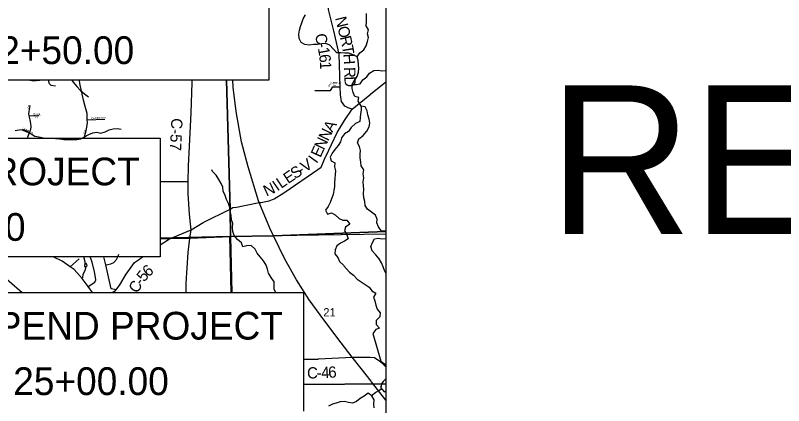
# Model space of a CAD drawing. Extents: x -37878.7 to -37844.7, y -19791.4 to -19769.4.
# Drawn here: x -37871.021 to -37867.14, y -19774.84 to -19772.87 of the extents above; entities that cross this region are included whole.
import ezdxf

# ---------------------------------------------------------------- set-up
doc = ezdxf.new("R2010")
doc.units = 0
for name, color, linetype in [('GM_X_City_Street', 7, 'Continuous'), ('GM_X_County_Road', 7, 'Continuous'), ('GM_X_County_Road_Text', 7, 'Continuous'), ('GM_X_Major_Lake', 7, 'Continuous'), ('GM_X_Minor_Lake', 7, 'Continuous'), ('GM_X_Minor_River', 7, 'Continuous'), ('GM_X_Section', 7, 'Continuous'), ('GM_X_Section_Text', 7, 'Continuous'), ('GM_X_State_Route', 7, 'Continuous'), ('GM_X_Township', 7, 'Continuous'), ('GM_X_Township_Road', 7, 'Continuous'), ('GM_X_Township_Subdivision', 7, 'Continuous'), ('GM_X_Township_Subdivision_Text', 7, 'Continuous'), ('GM_X_US_Route', 7, 'Continuous'), ('SH_Data', 7, 'Continuous'), ('TX_P_1', 7, 'Continuous')]:
    doc.layers.add(name, color=color, linetype=linetype)

msp = doc.modelspace()

# ---------------------------------------------------------------- linework, layer by layer
at = {"layer": 'GM_X_City_Street'}
for points in [[(-37870.6319, -19774.2693), (-37870.6537, -19774.2394), (-37870.6835, -19774.1987), (-37870.7235, -19774.1535), (-37870.7435, -19774.14), (-37870.7853, -19774.1117), (-37870.8292, -19774.0898)], [(-37870.7435, -19774.14), (-37870.6984, -19774.0985)], [(-37870.6537, -19774.2394), (-37870.6204, -19774.2173), (-37870.6146, -19774.2048), (-37870.6154, -19774.1939), (-37870.6212, -19774.1655), (-37870.6337, -19774.1162), (-37870.6432, -19774.0898)], [(-37870.5111, -19774.2563), (-37870.5369, -19774.2507), (-37870.5648, -19774.13), (-37870.5735, -19774.0898)], [(-37870.5648, -19774.13), (-37870.5544, -19774.1284), (-37870.5394, -19774.1251), (-37870.5235, -19774.1176), (-37870.5093, -19774.1025), (-37870.5026, -19774.0884), (-37870.4976, -19774.0758)], [(-37870.5327, -19774.2693), (-37870.5148, -19774.2586)], [(-37869.2072, -19774.5982), (-37869.1792, -19774.6162), (-37869.1585, -19774.6358)], [(-37869.1585, -19774.6358), (-37869.1504, -19774.6435)]]:
    msp.add_lwpolyline(points, dxfattribs=at)
at = {"layer": 'GM_X_County_Road'}
for points in [[(-37869.319, -19773.3445), (-37869.3398, -19773.3377), (-37869.3575, -19773.3294), (-37869.3736, -19773.3047), (-37869.3786, -19773.2714), (-37869.3799, -19773.2307), (-37869.3849, -19773.0657), (-37869.4128, -19772.9481), (-37869.4394, -19772.8412), (-37869.4519, -19772.4565), (-37869.4538, -19772.4162), (-37869.4608, -19772.3816)], [(-37870.1489, -19773.71), (-37870.1459, -19773.6301), (-37870.1407, -19773.5329), (-37870.1335, -19773.3623), (-37870.1286, -19773.2093), (-37870.1283, -19773.1975)], [(-37869.2267, -19773.269), (-37869.2266, -19773.2689), (-37869.1504, -19773.2056)], [(-37869.4529, -19773.5819), (-37869.3952, -19773.4624), (-37869.3584, -19773.4006), (-37869.319, -19773.3445), (-37869.2305, -19773.2721), (-37869.2267, -19773.269)], [(-37869.6604, -19773.7632), (-37869.4924, -19773.6483), (-37869.4768, -19773.6361), (-37869.4541, -19773.5846), (-37869.4537, -19773.5837), (-37869.4529, -19773.5819)], [(-37870.1489, -19773.71), (-37870.2888, -19773.711)], [(-37870.1334, -19773.9533), (-37870.1367, -19773.9231), (-37870.1422, -19773.8738), (-37870.1478, -19773.7705), (-37870.1489, -19773.71)], [(-37869.7801, -19773.8142), (-37869.7562, -19773.8106), (-37869.7396, -19773.8062), (-37869.7129, -19773.7965), (-37869.6655, -19773.7667), (-37869.6604, -19773.7632)], [(-37869.9224, -19773.8403), (-37869.9219, -19773.84), (-37869.9045, -19773.838), (-37869.7894, -19773.8156), (-37869.7801, -19773.8142)], [(-37870.2888, -19774.0279), (-37870.248, -19774.0013), (-37870.2371, -19773.9966), (-37870.1932, -19773.9774), (-37870.1334, -19773.9533), (-37870.0716, -19773.9158), (-37869.9361, -19773.8486), (-37869.9224, -19773.8403)], [(-37870.1393, -19773.9974), (-37870.1389, -19773.9947), (-37870.1334, -19773.9533)], [(-37870.3971, -19774.1033), (-37870.387, -19774.0962), (-37870.3781, -19774.0898)], [(-37870.5148, -19774.2586), (-37870.5111, -19774.2563), (-37870.4927, -19774.2309), (-37870.461, -19774.1768), (-37870.4187, -19774.1186), (-37870.3992, -19774.1048), (-37870.3971, -19774.1033)], [(-37869.489, -19774.6049), (-37869.3202, -19774.5956), (-37869.2976, -19774.5954)], [(-37869.2976, -19774.5954), (-37869.2293, -19774.5949), (-37869.2072, -19774.5982)], [(-37869.5652, -19774.6051), (-37869.4915, -19774.605), (-37869.489, -19774.6049)]]:
    msp.add_lwpolyline(points, dxfattribs=at)
at = {"layer": 'GM_X_Major_Lake'}
msp.add_line((-37869.3626, -19774.1343), (-37869.334, -19774.1659), dxfattribs=at)
for points in [[(-37869.1504, -19773.9578), (-37869.1517, -19773.9586), (-37869.171, -19773.9593), (-37869.186, -19773.9376), (-37869.195, -19773.9182), (-37869.1937, -19773.8988), (-37869.2023, -19773.8786), (-37869.2215, -19773.8641), (-37869.2415, -19773.8492), (-37869.2535, -19773.8294), (-37869.2564, -19773.81), (-37869.2601, -19773.791), (-37869.2626, -19773.7701), (-37869.2602, -19773.7496), (-37869.2631, -19773.7306), (-37869.2645, -19773.7105), (-37869.261, -19773.69), (-37869.2646, -19773.6695), (-37869.2611, -19773.6501), (-37869.275, -19773.6299), (-37869.2767, -19773.6102), (-37869.2789, -19773.5908), (-37869.2792, -19773.5711), (-37869.2775, -19773.5517), (-37869.2827, -19773.5327), (-37869.2924, -19773.5137), (-37869.2859, -19773.4943), (-37869.2646, -19773.4769), (-37869.2459, -19773.4546), (-37869.2347, -19773.433), (-37869.2305, -19773.4137), (-37869.2337, -19773.3935), (-37869.2412, -19773.373), (-37869.2448, -19773.3525), (-37869.2549, -19773.3327), (-37869.275, -19773.3288), (-37869.2736, -19773.3481), (-37869.2779, -19773.3675), (-37869.2791, -19773.3865), (-37869.2815, -19773.4058), (-37869.3032, -19773.4168), (-37869.3249, -19773.4368), (-37869.339, -19773.4569), (-37869.3588, -19773.4689), (-37869.3737, -19773.4882), (-37869.3787, -19773.508), (-37869.3906, -19773.5273), (-37869.4077, -19773.5466), (-37869.4203, -19773.5659), (-37869.4303, -19773.5856), (-37869.4259, -19773.6046), (-37869.4066, -19773.6153), (-37869.4083, -19773.635), (-37869.4046, -19773.6544), (-37869.4059, -19773.6738), (-37869.4075, -19773.6935), (-37869.4084, -19773.7152), (-37869.4082, -19773.7357), (-37869.4124, -19773.755), (-37869.416, -19773.774), (-37869.4241, -19773.796), (-37869.4306, -19773.8153), (-37869.441, -19773.8347), (-37869.454, -19773.8543), (-37869.4442, -19773.8738), (-37869.4249, -19773.8663), (-37869.4056, -19773.8777), (-37869.3857, -19773.8964), (-37869.3664, -19773.9045), (-37869.3471, -19773.9042), (-37869.3313, -19773.924), (-37869.3526, -19773.9391), (-37869.3581, -19773.9584), (-37869.3464, -19773.9779), (-37869.3394, -19773.9976), (-37869.3591, -19774.0097), (-37869.3781, -19774.0195), (-37869.3972, -19774.0342), (-37869.4064, -19774.0539), (-37869.4065, -19774.0733), (-37869.3915, -19774.0927)], [(-37869.1556, -19774.1583), (-37869.1638, -19774.1393), (-37869.1716, -19774.1191), (-37869.1829, -19774.0986), (-37869.2002, -19774.0791), (-37869.2182, -19774.0586), (-37869.2257, -19774.0376), (-37869.2168, -19774.0168), (-37869.2076, -19773.9978), (-37869.1879, -19773.9957), (-37869.1682, -19773.9976), (-37869.1504, -19773.9965)], [(-37869.3915, -19774.0927), (-37869.384, -19774.1133), (-37869.3633, -19774.1312), (-37869.3626, -19774.1343)], [(-37869.334, -19774.1659), (-37869.3133, -19774.1819), (-37869.2937, -19774.2018), (-37869.2737, -19774.2159), (-37869.2537, -19774.2285), (-37869.2345, -19774.2419), (-37869.2206, -19774.261), (-37869.2002, -19774.2728), (-37869.2117, -19774.2921), (-37869.2058, -19774.3119), (-37869.2006, -19774.3324), (-37869.1943, -19774.3526), (-37869.1789, -19774.372), (-37869.1798, -19774.3918), (-37869.1977, -19774.4114), (-37869.1989, -19774.4304), (-37869.1813, -19774.4495), (-37869.2006, -19774.4566), (-37869.2155, -19774.4767), (-37869.1755, -19774.6162), (-37869.1504, -19774.6352)], [(-37869.1504, -19774.171), (-37869.1556, -19774.1583)], [(-37869.2091, -19774.8511), (-37869.2097, -19774.8317), (-37869.2081, -19774.8109), (-37869.2201, -19774.7914), (-37869.2393, -19774.7769), (-37869.2591, -19774.7924), (-37869.2785, -19774.8037), (-37869.2983, -19774.8192), (-37869.3176, -19774.8275), (-37869.338, -19774.8239), (-37869.3588, -19774.8197), (-37869.38, -19774.8219), (-37869.4005, -19774.8275), (-37869.4199, -19774.8323), (-37869.4389, -19774.8429)]]:
    msp.add_lwpolyline(points, dxfattribs=at)
at = {"layer": 'GM_X_Minor_Lake'}
for p, q in [((-37870.6702, -19774.1276), (-37870.6711, -19774.1313)), ((-37869.1748, -19774.7499), (-37869.1582, -19774.7701))]:
    msp.add_line(p, q, dxfattribs=at)
for points in [[(-37870.6711, -19774.1313), (-37870.6711, -19774.1351), (-37870.6711, -19774.1374), (-37870.6658, -19774.1378), (-37870.6586, -19774.134), (-37870.6608, -19774.1276), (-37870.6627, -19774.1234), (-37870.6699, -19774.1253), (-37870.6702, -19774.1276)], [(-37869.1504, -19774.7074), (-37869.1533, -19774.7086), (-37869.1628, -19774.718), (-37869.172, -19774.7298), (-37869.174, -19774.7419), (-37869.1763, -19774.7464), (-37869.1748, -19774.7499)], [(-37869.1582, -19774.7701), (-37869.1504, -19774.7664)]]:
    msp.add_lwpolyline(points, dxfattribs=at)
at = {"layer": 'GM_X_Minor_River'}
for points in [[(-37869.2946, -19773.0788), (-37869.315, -19773.0688), (-37869.3365, -19773.0619), (-37869.357, -19773.061), (-37869.3774, -19773.0594), (-37869.3967, -19773.059), (-37869.4328, -19773.0208), (-37869.4524, -19773.0124), (-37869.4733, -19773.0138), (-37869.4941, -19773.0168), (-37869.5157, -19773.0182), (-37869.5369, -19773.0204), (-37869.5585, -19773.0176), (-37869.5781, -19773.0065), (-37869.5871, -19772.9871), (-37869.5888, -19772.9658), (-37869.5864, -19772.9457), (-37869.581, -19772.9264), (-37869.5733, -19772.9074), (-37869.5671, -19772.8881), (-37869.5553, -19772.8668)], [(-37869.3201, -19773.2192), (-37869.3086, -19773.1995), (-37869.2937, -19773.1791), (-37869.2871, -19773.1578), (-37869.2863, -19773.1388), (-37869.2873, -19773.1195), (-37869.2887, -19773.0989), (-37869.2946, -19773.0788), (-37869.2812, -19773.0587), (-37869.2611, -19773.0444), (-37869.2484, -19773.0235), (-37869.243, -19773.0015), (-37869.2379, -19772.9822), (-37869.242, -19772.9632), (-37869.2373, -19772.9427), (-37869.2482, -19772.9237), (-37869.2465, -19772.9005), (-37869.2471, -19772.8804), (-37869.2478, -19772.8614)], [(-37869.275, -19773.3288), (-37869.2896, -19773.3036), (-37869.2868, -19773.2843), (-37869.3061, -19773.2796), (-37869.3143, -19773.2595), (-37869.3198, -19773.2389), (-37869.3201, -19773.2192), (-37869.2993, -19773.2189), (-37869.2796, -19773.216), (-37869.2666, -19773.1959), (-37869.2456, -19773.1812), (-37869.2319, -19773.1619), (-37869.2102, -19773.1487), (-37869.1886, -19773.1465), (-37869.1693, -19773.15), (-37869.1504, -19773.149)], [(-37870.9477, -19773.1975), (-37870.9367, -19773.1996), (-37870.9166, -19773.1993), (-37870.8967, -19773.1975)], [(-37870.7358, -19773.1975), (-37870.7289, -19773.2067), (-37870.7101, -19773.2295), (-37870.692, -19773.249), (-37870.6713, -19773.2658), (-37870.6521, -19773.2811)], [(-37871.0212, -19773.4522), (-37871.0022, -19773.4473), (-37870.9799, -19773.4467), (-37870.9606, -19773.4543), (-37870.9414, -19773.4681), (-37870.9222, -19773.48), (-37870.9029, -19773.4842), (-37870.8794, -19773.4881), (-37870.859, -19773.4905), (-37870.8393, -19773.491), (-37870.8189, -19773.4922), (-37870.7973, -19773.4942), (-37870.7754, -19773.4962), (-37870.753, -19773.4963), (-37870.7307, -19773.4972), (-37870.7102, -19773.4973), (-37870.6905, -19773.4936), (-37870.6712, -19773.4834), (-37870.6506, -19773.4721), (-37870.629, -19773.4639), (-37870.6097, -19773.4606), (-37870.5893, -19773.4652), (-37870.5676, -19773.4577), (-37870.5479, -19773.4487), (-37870.5267, -19773.4431), (-37870.5066, -19773.442), (-37870.4873, -19773.4444)], [(-37869.7047, -19774.2693), (-37869.7143, -19774.2546), (-37869.7134, -19774.2356), (-37869.7129, -19774.2147), (-37869.7291, -19774.193), (-37869.7426, -19774.172), (-37869.7481, -19774.1519), (-37869.7537, -19774.131), (-37869.7683, -19774.1096), (-37869.7837, -19774.0898), (-37869.7991, -19774.0708), (-37869.8103, -19774.0502), (-37869.8307, -19774.0323), (-37869.8523, -19774.0345), (-37869.8712, -19774.0382), (-37869.8794, -19774.0191), (-37869.899, -19774.0016), (-37869.9155, -19773.9818), (-37869.9222, -19773.962), (-37869.9244, -19773.9419), (-37869.9231, -19773.9217), (-37869.929, -19773.9016), (-37869.9308, -19773.8814), (-37869.9367, -19773.8617), (-37869.9374, -19773.84), (-37869.9437, -19773.8199), (-37869.9553, -19773.8004), (-37869.9608, -19773.7795), (-37869.9709, -19773.7578), (-37869.9727, -19773.7381), (-37869.9813, -19773.7183), (-37869.9936, -19773.6981), (-37870.006, -19773.6772), (-37870.0248, -19773.6581), (-37870.0293, -19773.6493)], [(-37870.675, -19774.0898), (-37870.6746, -19774.0937), (-37870.6706, -19774.1135), (-37870.6699, -19774.1253)], [(-37870.6658, -19774.1378), (-37870.6697, -19774.1598), (-37870.6801, -19774.1791), (-37870.6817, -19774.1951)], [(-37869.2229, -19774.7893), (-37869.201, -19774.7729), (-37869.1813, -19774.7616), (-37869.1709, -19774.7546)]]:
    msp.add_lwpolyline(points, dxfattribs=at)
at = {"layer": 'GM_X_Section'}
for points in [[(-37869.9314, -19774.2693), (-37869.9382, -19773.9854), (-37869.1504, -19773.9726)], [(-37870.2888, -19773.9928), (-37869.9382, -19773.9854), (-37869.9314, -19774.2693)], [(-37869.1504, -19774.7302), (-37869.5652, -19774.7338)], [(-37869.5652, -19774.7338), (-37869.1504, -19774.7302)]]:
    msp.add_lwpolyline(points, dxfattribs=at)
at = {"layer": 'GM_X_State_Route'}
for points in [[(-37869.7924, -19773.806), (-37869.8444, -19773.635), (-37869.8783, -19773.5087), (-37869.9052, -19773.3557), (-37869.9209, -19773.2328), (-37869.9232, -19773.1975)], [(-37869.2216, -19774.7207), (-37869.224, -19774.7176), (-37869.2751, -19774.6534), (-37869.3202, -19774.5956), (-37869.3752, -19774.5238), (-37869.4636, -19774.4065), (-37869.5363, -19774.3068), (-37869.6009, -19774.2059), (-37869.6598, -19774.1005), (-37869.7171, -19773.9825), (-37869.7358, -19773.9441), (-37869.7894, -19773.8156), (-37869.7924, -19773.806)], [(-37869.1504, -19774.8123), (-37869.2216, -19774.7207)]]:
    msp.add_lwpolyline(points, dxfattribs=at)
at = {"layer": 'GM_X_Township'}
for points in [[(-37869.9552, -19773.1975), (-37869.9361, -19773.8486), (-37869.9338, -19773.9865), (-37870.1389, -19773.9947), (-37870.2371, -19773.9966), (-37870.2888, -19773.9975)], [(-37869.1504, -19773.9613), (-37869.7171, -19773.9825), (-37869.9338, -19773.9865), (-37869.9361, -19773.8486), (-37869.9552, -19773.1975)], [(-37869.927, -19774.2693), (-37869.9338, -19773.9865), (-37869.7171, -19773.9825), (-37869.1504, -19773.9613)], [(-37870.2888, -19773.9975), (-37870.2371, -19773.9966), (-37870.1389, -19773.9947), (-37869.9338, -19773.9865), (-37869.927, -19774.2693)]]:
    msp.add_lwpolyline(points, dxfattribs=at)
at = {"layer": 'GM_X_Township_Road'}
msp.add_lwpolyline([(-37870.158, -19774.2693), (-37870.1582, -19774.2227), (-37870.1484, -19774.0665), (-37870.1393, -19773.9974)], dxfattribs=at)
at = {"layer": 'GM_X_Township_Subdivision'}
for points in [[(-37870.8177, -19773.227), (-37870.8408, -19773.2243), (-37870.8488, -19773.2166), (-37870.8511, -19773.2056), (-37870.8512, -19773.1975)], [(-37870.6736, -19773.4907), (-37870.6629, -19773.4523), (-37870.6593, -19773.4349), (-37870.6572, -19773.4118), (-37870.6577, -19773.3969), (-37870.6585, -19773.3658), (-37870.6678, -19773.331), (-37870.6771, -19773.2982), (-37870.6947, -19773.2139), (-37870.6969, -19773.1975)], [(-37869.5076, -19773.25), (-37869.429, -19773.25), (-37869.4178, -19773.2307), (-37869.3799, -19773.2307)], [(-37870.9592, -19773.4907), (-37870.9544, -19773.475), (-37870.95, -19773.4638), (-37870.9436, -19773.4448), (-37870.9418, -19773.4323), (-37870.9423, -19773.4167), (-37870.9466, -19773.3973), (-37870.9505, -19773.377), (-37870.9522, -19773.3675), (-37870.9513, -19773.3563), (-37870.9462, -19773.3252)], [(-37870.9505, -19773.377), (-37870.903, -19773.3761)], [(-37870.6577, -19773.3969), (-37870.5692, -19773.3939)], [(-37870.9885, -19773.4474), (-37870.95, -19773.4638)]]:
    msp.add_lwpolyline(points, dxfattribs=at)
at = {"layer": 'GM_X_US_Route'}
msp.add_lwpolyline([(-37871.119, -19774.1545), (-37870.9866, -19774.2693)], dxfattribs=at)
at = {"layer": 'SH_Data'}
msp.add_line((-37869.1504, -19770.3854), (-37869.1504, -19777.3854), dxfattribs=at)
at = {"layer": 'TX_P_1'}
for p, q in [((-37869.74, -19772.5985), (-37869.74, -19773.1975)), ((-37869.74, -19773.1975), (-37871.7188, -19773.1975)), ((-37872.2676, -19773.4907), (-37870.2888, -19773.4907)), ((-37870.2888, -19773.4907), (-37870.2888, -19774.0898)), ((-37870.2888, -19774.0898), (-37872.2676, -19774.0898)), ((-37871.544, -19774.2693), (-37869.5652, -19774.2693)), ((-37869.5652, -19774.2693), (-37869.5652, -19774.8684))]:
    msp.add_line(p, q, dxfattribs=at)

# ---------------------------------------------------------------- texts
at = {"layer": 'GM_X_County_Road_Text'}
for s, height, rotation, p in [('N', 0.0568, 283.4813, (-37869.406, -19772.8831)), ('O', 0.0568, 283.5699, (-37869.3943, -19772.9318)), ('C', 0.0568, 282.9187, (-37869.5087, -19772.9686)), ('R', 0.0568, 283.3836, (-37869.3826, -19772.9804)), ('-', 0.0568, 282.2232, (-37869.4983, -19773.0139)), ('1', 0.0568, 280.3021, (-37869.4935, -19773.0362)), ('T', 0.0568, 279.8801, (-37869.372, -19773.0249)), ('6', 0.0568, 277.258, (-37869.4873, -19773.0698)), ('H', 0.0568, 274.266, (-37869.3649, -19773.0653)), ('1', 0.0568, 272.8008, (-37869.483, -19773.1034)), ('R', 0.0568, 271.7371, (-37869.3606, -19773.132)), ('D', 0.0568, 271.8925, (-37869.3592, -19773.1788)), ('C-57', 0.05682, 267.2726, (-37870.2328, -19773.3883)), ('N', 0.0568, 64.3237, (-37869.4412, -19773.508)), ('A', 0.0568, 60.8683, (-37869.42, -19773.4637)), ('N', 0.0568, 64.8084, (-37869.4625, -19773.5531)), ('E', 0.0568, 65.7027, (-37869.4799, -19773.5916)), ('V', 0.0568, 33.9555, (-37869.5569, -19773.6644)), ('I', 0.0568, 54.0608, (-37869.4999, -19773.6214)), ('S', 0.0568, 33.9141, (-37869.6081, -19773.6988)), ('E', 0.0568, 33.9165, (-37869.6434, -19773.7226)), ('-', 0.0568, 33.9087, (-37869.5763, -19773.6775)), ('I', 0.0568, 34.9387, (-37869.6976, -19773.7595)), ('L', 0.0568, 33.9082, (-37869.6787, -19773.7463)), ('N', 0.0568, 24.9031, (-37869.7524, -19773.7859)), ('6', 0.0568, 39.7842, (-37870.35, -19774.1936)), ('5', 0.0568, 52.3058, (-37870.3691, -19774.219)), ('C', 0.0568, 59.2762, (-37870.4048, -19774.277)), ('-', 0.0568, 56.5113, (-37870.3814, -19774.2375)), ('6', 0.0568, 3.5014, (-37869.4391, -19774.7005)), ('C', 0.0568, 0.3571, (-37869.5474, -19774.7034)), ('-', 0.0568, 1.9219, (-37869.4991, -19774.7031)), ('4', 0.0568, 2.8584, (-37869.4747, -19774.7023))]:
    msp.add_text(s, height=height, rotation=rotation, dxfattribs=at).set_placement(p)
at = {"layer": 'GM_X_Section_Text'}
msp.add_text('21', height=0.04186, rotation=0, dxfattribs=at).set_placement((-37869.4654, -19774.3902))
at = {"layer": 'GM_X_Township_Subdivision_Text'}
for s, rotation, p in [('H', 10.0421, (-37869.4221, -19773.2174)), ('E', 0, (-37869.4143, -19773.216)), ('R', 0, (-37869.4076, -19773.216)), ('I', 0, (-37869.4001, -19773.216)), ('N', 0, (-37869.396, -19773.216)), ('E', 0, (-37869.3876, -19773.216)), ('C', 60.2529, (-37869.4351, -19773.2324)), ('A', 50.2107, (-37869.4317, -19773.2263)), ('T', 30.1264, (-37869.427, -19773.2204)), ('DR', 0, (-37869.42, -19773.229)), ('DR', 81.0318, (-37870.95, -19773.3411)), ('BASIL', 0, (-37870.9292, -19773.3746)), ('PL', 0, (-37870.9192, -19773.3907)), ('DEEPAK', 3.1224, (-37870.6359, -19773.3947)), ('DR', 0, (-37870.5842, -19773.3922)), ('LEXIE LN', 336.3179, (-37870.9868, -19773.4448)), ('DR', 75.2635, (-37870.6684, -19773.4684))]:
    msp.add_text(s, height=0.00947, rotation=rotation, dxfattribs=at).set_placement(p)
at = {"layer": 'SH_Data'}
msp.add_text('RESERVE GREENWAY-', height=0.75, dxfattribs=at).set_placement((-37868.3275, -19773.9738))
at = {"layer": 'TX_P_1'}
for s, p in [('STA. 92+50.00', (-37871.6748, -19773.1161)), ('SUSPEND PROJECT', (-37872.2236, -19773.7283)), ('STA. 53+75.00', (-37872.2236, -19774.0083)), ('SUSPEND PROJECT', (-37871.5, -19774.5069)), ('STA. 25+00.00', (-37871.5, -19774.7869))]:
    msp.add_text(s, height=0.14, rotation=360, dxfattribs=at).set_placement(p)

doc.saveas('drawing.dxf')
